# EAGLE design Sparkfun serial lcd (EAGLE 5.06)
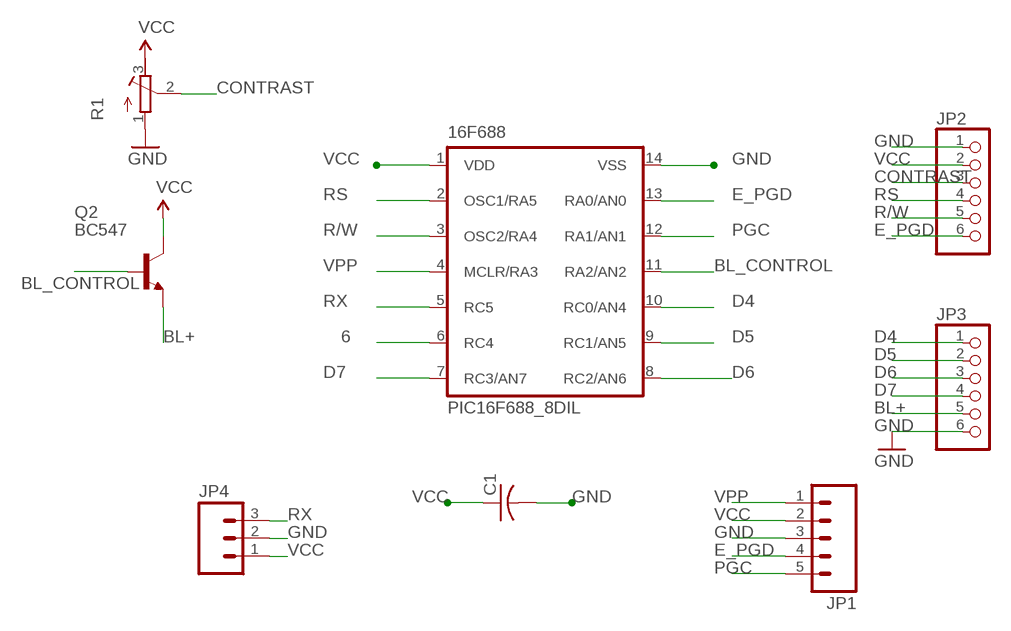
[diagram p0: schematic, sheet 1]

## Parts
16F688  PIC16F688_8DIL  PIC16F8DIL  [DIL14]
C1  C-US050-024X044  [C050-024X044]
JP1  M05LOCK  [1X05_LOCK]
JP2  PINHD-1X6  [1X06]
JP3  PINHD-1X6  [1X06]
JP4  M03SCREW  [SCREWTERMINAL-3.5MM-3]
Q2  BC547  [TO92]
R1  R-TRIMM3296W  [RTRIM3296W]

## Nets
6: 16F688.6(RC4)
BL+: JP3.5 Q2.1(E)
BL_CONTROL: 16F688.11(RA2/AN2) Q2.2(B)
CONTRAST: JP2.3 R1.2(S)
D4: 16F688.10(RC0/AN4) JP3.1
D5: 16F688.9(RC1/AN5) JP3.2
D6: 16F688.8(RC2/AN6) JP3.3
D7: 16F688.7(RC3/AN7) JP3.4
E_PGD: 16F688.13(RA0/AN0) JP1.4 JP2.6
GND: 16F688.14(VSS) C1.2 JP1.3 JP2.1 JP3.6 JP4.2 R1.1(E)
PGC: 16F688.12(RA1/AN1) JP1.5
R/W: 16F688.3(OSC2/RA4) JP2.5
RS: 16F688.2(OSC1/RA5) JP2.4
RX: 16F688.5(RC5) JP4.3
VCC: 16F688.1(VDD) C1.1 JP1.2 JP2.2 JP4.1 Q2.3(C) R1.3(A)
VPP: 16F688.4(MCLR/RA3) JP1.1

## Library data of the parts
16F688 = pic16f6xx_14pin:PIC16F8*: MICROCONTROLLER 14-Pin, 8-Bit PIC16F8X Family - CMOS Flash Pin Compatible : 16F630, 16F676, 16F684, 16F688 Keywords: PIC16F630, PIC16F676, PIC16F684, PIC16F688
C1 = rcl-2:C-US: CAPACITOR, American symbol
JP1 = 1-SparkFun:M05: Header 5 Standard 5-pin 0.1" header. Use with straight break away headers (SKU : PRT-00116), right angle break away headers (PRT-00553), swiss pins (PRT-00743), machine pins (PRT-00117), and female headers (PRT-00115). Molex polarized connector foot print use with SKU : PRT-08230 with associated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
JP2 JP3 = pinhead:PINHD-1X6: PIN HEADER
JP4 = 1-SparkFun:M03: Header 3 Standard 3-pin 0.1" header. Use with straight break away headers (SKU : PRT-00116), right angle break away headers (PRT-00553), swiss pins (PRT-00743), machine pins (PRT-00117), and female headers (PRT-00115). Molex polarized connector foot print use with SKU : PRT-08232 with associated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
Q2 = transistor-npn:BC547*: NPN Transistor
R1 = rcl-2:R-TRIMM: Trimm resistor

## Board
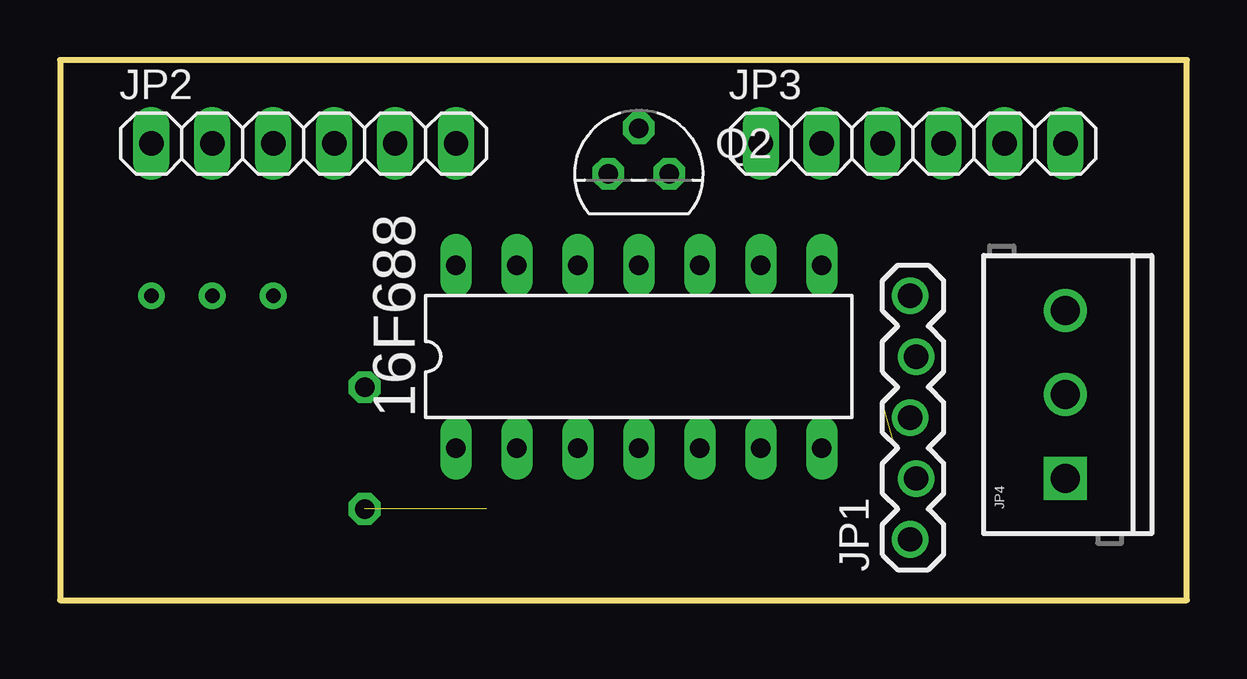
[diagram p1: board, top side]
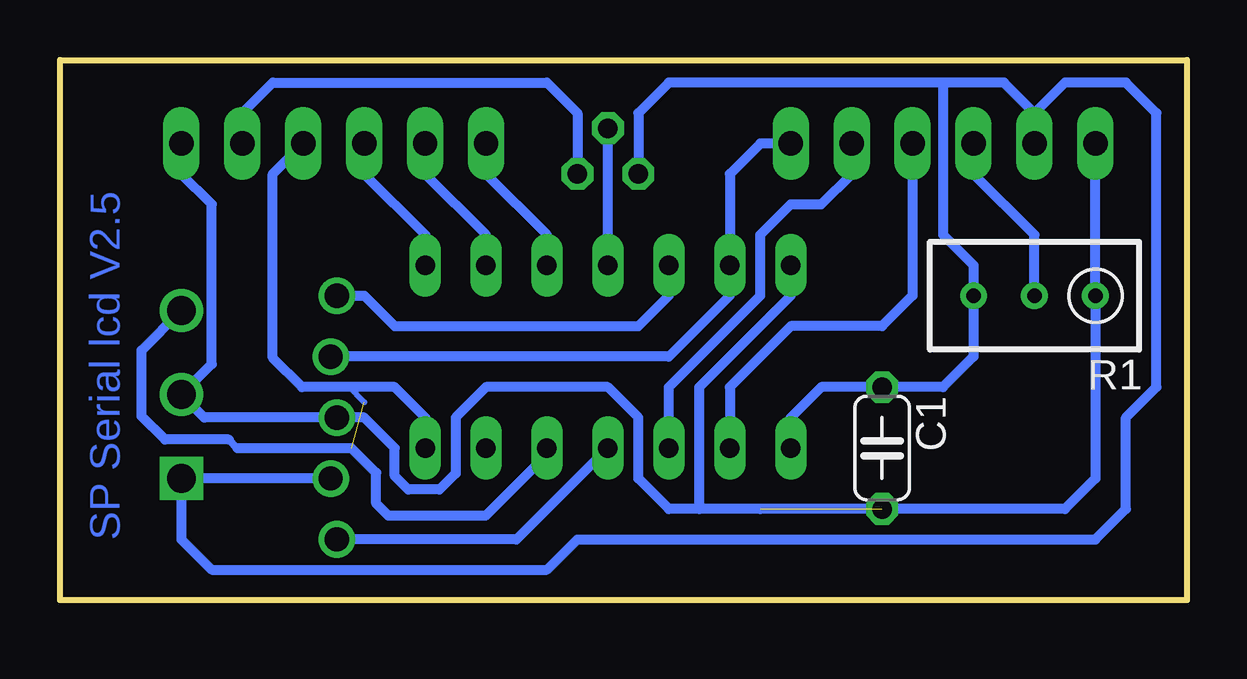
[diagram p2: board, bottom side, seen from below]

Size 46.97 x 22.53 mm. Coordinates in mm from the lower left corner, seen from the top.
Outline: 0,0 46.97,0 46.97,22.53 0,22.53 0,0
Copper layers (1*16): Top 0.035mm / dielectric 1.5mm / Bottom 0.035mm
Design rules "default": minimum track width 10mil, minimum drill 24mil, track to track 8mil, track to pad 8mil, pad to pad 8mil, via to via 8mil, smd to smd 8mil, copper to edge 40mil, drill to drill 8mil, minimum pad ring 10mil, minimum via ring 8mil, stop-mask expansion 4mil, vias tented up to drill 0mil, thermal gap 10mil

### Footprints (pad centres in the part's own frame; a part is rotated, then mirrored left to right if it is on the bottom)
DIL14 = drill 0.813 long: 1 -10.16,-3.81; 2 -7.62,-3.81; 3 -5.08,-3.81; 4 -2.54,-3.81; 5 0,-3.81; 6 2.54,-3.81; 7 5.08,-3.81; 8 5.08,3.81; 9 2.54,3.81; 10 0,3.81; 11 -2.54,3.81; 12 -5.08,3.81; 13 -7.62,3.81; 14 -10.16,3.81
C050-024X044 = drill 0.813 octagon: 1 -2.54,0; 2 2.54,0
1X05_LOCK = drill 1.016 round: 1 0,0.127; 2 2.54,-0.127; 3 5.08,0.127; 4 7.62,-0.127; 5 10.16,0.127
1X06 = drill 1.016 long: 1 -6.35,0; 2 -3.81,0; 3 -1.27,0; 4 1.27,0; 5 3.81,0; 6 6.35,0
SCREWTERMINAL-3.5MM-3 = drill 1.2 square: 1 0,0 | drill 1.2 round: 2 3.5,0; 3 7,0
TO92 = drill 0.813 octagon: 1 1.27,0; 2 0,1.905; 3 -1.27,0
RTRIM3296W = drill 0.61 round: 1 0,-2.54; 2 0,0; 3 0,2.54

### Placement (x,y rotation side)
16F688  26.67,10.16 0 top
C1  12.7,6.35 270 bottom
JP1  35.56,2.54 90 top
JP2  10.16,19.05 0 top
JP3  35.56,19.05 0 top
JP4  41.91,5.08 90 top
Q2  24.13,17.78 0 top
R1  6.35,12.7 90 bottom

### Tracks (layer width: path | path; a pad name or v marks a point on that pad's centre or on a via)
BL+
  Bottom 0.406: JP3.5 39.37,20.32 38.1,21.59 26.67,21.59 25.4,20.32 Q2.1
BL_CONTROL
  Bottom 0.406: 16F688.11 Q2.2
CONTRAST
  Bottom 0.406: R1.2 6.35,15.24 8.89,17.78 JP2.3
D4
  Bottom 0.406: 16F688.10 26.67,15.24 29.21,17.78 JP3.1
D5
  Bottom 0.406: 16F688.9 29.21,15.24 31.75,17.78 JP3.2
D6
  Bottom 0.406: 16F688.8 31.75,15.24 34.29,17.78 JP3.3
D7
  Bottom 0.406: 16F688.7 31.75,7.62 33.02,8.89 36.88,8.89 38.1,10.11 38.1,17.78 JP3.4
E_PGD
  Bottom 0.406: JP1.4 21.59,10.16 19.05,12.7 16F688.13 19.05,17.78 17.78,19.05 JP2.6
GND  (1 unrouted)
  Bottom 0.305: 16.51,12.7 16F688.14
  Bottom 0.406: JP3.6 41.91,17.78 40.64,16.51 40.64,9.85 JP4.2 40.95,7.62 JP1.3 34.29,7.62 33.02,6.35 33.02,5.18 32.46,4.62 31.15,4.62 30.48,5.29 30.48,7.62 29.21,8.89 24.13,8.89 22.86,7.62 22.86,5.08 21.59,3.81 20.32,3.81 | 20.32,3.81 20.32,8.89 16.51,12.7 | 20.32,3.81 17.78,3.81 5.08,3.81 3.81,5.08 R1.1 JP2.1
PGC
  Bottom 0.406: JP1.5 34.29,12.7 33.02,11.43 22.86,11.43 21.59,12.7 16F688.12
R/W
  Bottom 0.406: 16F688.3 21.59,8.89 17.78,12.7 17.78,15.24 16.51,16.51 15.24,16.51 13.97,17.78 JP2.5
RS
  Bottom 0.406: JP2.4 11.43,12.7 12.7,11.43 16.51,11.43 19.05,8.89 16F688.2
RX  (1 unrouted)
  Bottom 0.254: 34.29,8.25 34.92,8.89
  Bottom 0.305: 39.57,6.34 39.93,6.7
  Bottom 0.406: 16F688.5 26.67,6.09 29.24,3.52 33.28,3.52 33.79,4.03 33.79,5.31 34.81,6.34 39.57,6.34 | 39.93,6.7 42.59,6.7 43.57,7.67 43.57,10.42 JP4.3
VCC
  Bottom 0.406: 16F688.1 16.51,7.62 15.24,8.89 C1.1 10.16,8.89 8.89,10.16 R1.3 8.89,13.97 10.16,15.24 10.16,21.59 | 6.35,20.32 5.08,21.59 2.54,21.59 1.27,20.32 1.27,8.89 2.54,7.62 2.54,3.81 3.81,2.54 25.4,2.54 26.67,1.27 40.64,1.27 41.91,2.54 JP4.1 JP1.2 | 6.35,20.32 JP2.2 | Q2.3 22.86,20.32 21.59,21.59 10.16,21.59 | 10.16,21.59 7.62,21.59 6.35,20.32
VPP
  Bottom 0.406: 16F688.4 27.94,2.54 JP1.1

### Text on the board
Bottom: SP Serial lcd V2.5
